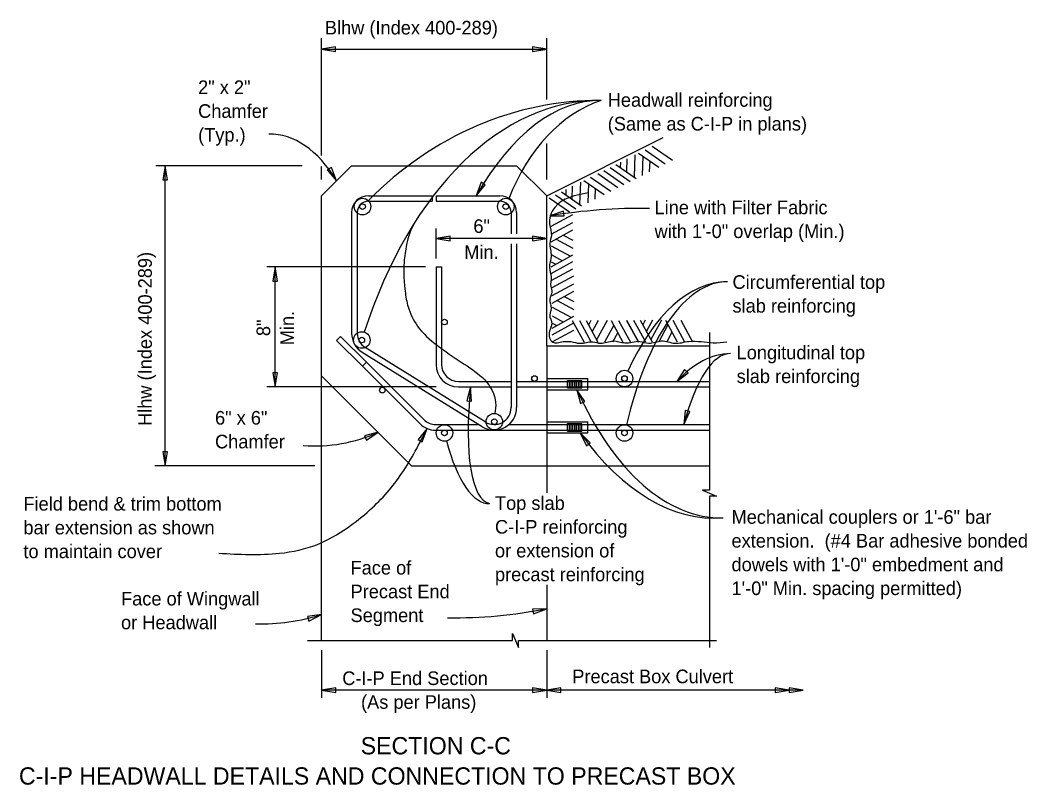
# Model space of a CAD drawing. Extents: x 10575.8 to 10602.6, y 76426.7 to 76442.6.
# Drawn here: x 10576.34 to 10581.93, y 76432.51 to 76436.75 of the extents above; entities that cross this region are included whole.
import ezdxf

# ---------------------------------------------------------------- set-up
doc = ezdxf.new("R2010")
doc.units = 0
for name, color, linetype in [('AdhocPoint_dp', 7, 'Continuous'), ('Miscellaneous', 7, 'Continuous'), ('PlotBorder_dp', 7, 'Continuous'), ('SheetBorder_dp', 7, 'Continuous'), ('TextMisc', 7, 'Continuous')]:
    doc.layers.add(name, color=color, linetype=linetype)

msp = doc.modelspace()

# ---------------------------------------------------------------- linework, layer by layer
at = {"layer": 'AdhocPoint_dp'}
for p, q in [((10578.2711, 76435.7777), (10578.6253, 76435.7777)), ((10578.2711, 76435.7465), (10578.6253, 76435.7465)), ((10578.6253, 76435.7777), (10578.6253, 76435.7465)), ((10578.6461, 76435.7777), (10578.6461, 76435.7465)), ((10578.6461, 76435.7777), (10579.0003, 76435.7777)), ((10578.6461, 76435.7465), (10579.0003, 76435.7465)), ((10578.1774, 76435.684), (10578.1774, 76435.014)), ((10578.2086, 76435.684), (10578.2086, 76435.014)), ((10579.0628, 76435.684), (10579.0628, 76435.5667)), ((10579.094, 76435.684), (10579.094, 76435.5667)), ((10579.0628, 76435.5107), (10579.0628, 76434.6006)), ((10579.094, 76435.5101), (10579.094, 76434.6006)), ((10578.6462, 76435.382), (10578.6462, 76434.8403)), ((10578.6462, 76435.382), (10578.6774, 76435.382)), ((10578.6774, 76435.382), (10578.6774, 76434.8403)), ((10578.094, 76434.9743), (10578.1161, 76434.9963)), ((10578.2381, 76434.8302), (10578.094, 76434.9743)), ((10578.2602, 76434.8523), (10578.1161, 76434.9963)), ((10578.9032, 76434.4944), (10578.2366, 76434.9077)), ((10578.9196, 76434.5209), (10578.253, 76434.9342)), ((10578.2381, 76434.8302), (10578.2602, 76434.8523)), ((10578.5782, 76434.5343), (10578.2602, 76434.8523)), ((10578.5561, 76434.5122), (10578.2381, 76434.8302)), ((10578.7712, 76434.7465), (10579.0628, 76434.7465)), ((10579.094, 76434.7465), (10580.1643, 76434.7465)), ((10578.7712, 76434.7153), (10579.0628, 76434.7153)), ((10579.094, 76434.7153), (10580.1643, 76434.7153)), ((10579.1116, 76434.7153), (10579.2816, 76434.7153)), ((10578.6445, 76434.5068), (10578.8831, 76434.5068)), ((10578.6445, 76434.4756), (10580.1643, 76434.4756)), ((10579.0517, 76434.5068), (10580.1643, 76434.5068))]:
    msp.add_line(p, q, dxfattribs=at)
for centre in [(10578.238, 76435.7172), (10579.0335, 76435.7172), (10578.693, 76435.076), (10578.2341, 76434.9759), (10579.193, 76434.7621), (10579.693, 76434.7621), (10578.3484, 76434.6978), (10578.9699, 76434.5224), (10578.693, 76434.46), (10579.693, 76434.46)]:
    msp.add_circle(centre, 0.0156, dxfattribs=at)
for centre, radius, start, end in [((10578.2711, 76435.684), 0.0937, 90.0004, 179.9995), ((10578.2711, 76435.684), 0.0625, 90, 180), ((10579.0003, 76435.684), 0.0937, 0.0004, 90.0004), ((10579.0003, 76435.684), 0.0625, 0, 90), ((10578.3024, 76435.014), 0.125, 180, 238.196), ((10578.3024, 76435.014), 0.0938, 180, 238.1963), ((10578.7712, 76434.8403), 0.125, 180, 269.9925), ((10578.7712, 76434.8403), 0.0938, 180, 270), ((10578.969, 76434.6006), 0.125, 238.1961, 0), ((10578.969, 76434.6006), 0.0938, 238.1961, 0), ((10578.6445, 76434.6006), 0.125, 225, 269.9925), ((10578.6445, 76434.6006), 0.0938, 225, 270)]:
    msp.add_arc(centre, radius, start, end, dxfattribs=at)
at = {"layer": 'Miscellaneous'}
for p, q in [((10579.2607, 76435.7777), (10579.9073, 76436.101)), ((10579.8073, 76436.0324), (10579.9195, 76435.9546)), ((10579.8469, 76436.0522), (10579.9592, 76435.9744)), ((10579.67, 76435.9637), (10579.669, 76435.9353)), ((10579.7058, 76435.9816), (10579.7033, 76435.9115)), ((10579.7504, 76436.0039), (10579.7457, 76435.882)), ((10579.7702, 76436.0138), (10579.8827, 76435.9361)), ((10579.7951, 76435.9966), (10579.7913, 76435.8905)), ((10579.8329, 76435.9706), (10579.8306, 76435.9101)), ((10579.5775, 76435.9175), (10579.6897, 76435.8396)), ((10579.6125, 76435.935), (10579.7247, 76435.8572)), ((10579.6456, 76435.9515), (10579.7578, 76435.8737)), ((10579.4477, 76435.8524), (10579.443, 76435.7305)), ((10579.4675, 76435.8623), (10579.58, 76435.7846)), ((10579.5046, 76435.8808), (10579.6168, 76435.803)), ((10579.5442, 76435.9006), (10579.6565, 76435.8228)), ((10579.3429, 76435.8), (10579.455, 76435.7221)), ((10579.3673, 76435.8122), (10579.3663, 76435.7837)), ((10579.4031, 76435.8301), (10579.4006, 76435.7599)), ((10579.4924, 76435.8451), (10579.4886, 76435.7389)), ((10579.5301, 76435.819), (10579.5279, 76435.7585)), ((10579.2748, 76435.7659), (10579.387, 76435.6881)), ((10579.3098, 76435.7834), (10579.422, 76435.7056)), ((10579.2863, 76435.608), (10579.4061, 76435.6736)), ((10579.2863, 76435.5637), (10579.4061, 76435.6293)), ((10579.2863, 76435.5222), (10579.4061, 76435.5881)), ((10579.3128, 76435.5368), (10579.4061, 76435.4859)), ((10579.3531, 76435.5589), (10579.4061, 76435.5299)), ((10579.2863, 76435.5001), (10579.3933, 76435.4414)), ((10579.2863, 76435.4502), (10579.348, 76435.4166)), ((10579.2863, 76435.3829), (10579.4061, 76435.4484)), ((10579.2863, 76435.3459), (10579.4061, 76435.4115)), ((10579.2863, 76435.4102), (10579.3114, 76435.3966)), ((10579.2863, 76435.3068), (10579.4061, 76435.3723)), ((10579.2917, 76435.2674), (10579.4115, 76435.333)), ((10579.2917, 76435.2231), (10579.4115, 76435.2886)), ((10579.2917, 76435.1816), (10579.4115, 76435.2475)), ((10579.3182, 76435.1962), (10579.4115, 76435.1453)), ((10579.3584, 76435.2183), (10579.4115, 76435.1892)), ((10579.2917, 76435.1594), (10579.3986, 76435.1007)), ((10579.2917, 76435.1096), (10579.3533, 76435.076)), ((10579.2917, 76435.0422), (10579.4115, 76435.1078)), ((10579.2917, 76435.0053), (10579.4115, 76435.0708)), ((10579.2917, 76435.0696), (10579.3167, 76435.0559)), ((10579.4031, 76435.0844), (10579.4686, 76434.9646)), ((10579.4423, 76435.0844), (10579.5078, 76434.9646)), ((10579.4793, 76435.0844), (10579.5448, 76434.9646)), ((10579.5066, 76435.0844), (10579.4929, 76435.0593)), ((10579.5466, 76435.0844), (10579.513, 76435.0227)), ((10579.5964, 76435.0844), (10579.5377, 76434.9774)), ((10579.6186, 76435.0844), (10579.6845, 76434.9646)), ((10579.6601, 76435.0844), (10579.7256, 76434.9646)), ((10579.7044, 76435.0864), (10579.77, 76434.9666)), ((10579.7044, 76435.0844), (10579.77, 76434.9646)), ((10579.7436, 76435.0864), (10579.8092, 76434.9666)), ((10579.7806, 76435.0864), (10579.8461, 76434.9666)), ((10579.8079, 76435.0864), (10579.7943, 76435.0613)), ((10579.8479, 76435.0864), (10579.8143, 76435.0247)), ((10579.8977, 76435.0864), (10579.8391, 76434.9794)), ((10579.9199, 76435.0864), (10579.9858, 76434.9666)), ((10579.9614, 76435.0864), (10580.027, 76434.9666)), ((10580.0057, 76435.0864), (10580.0713, 76434.9666)), ((10579.2917, 76434.9661), (10579.4115, 76435.0316)), ((10579.6332, 76435.0579), (10579.5823, 76434.9646)), ((10579.6553, 76435.0176), (10579.6262, 76434.9646)), ((10579.9345, 76435.0599), (10579.8836, 76434.9666)), ((10579.9566, 76435.0197), (10579.9275, 76434.9666)), ((10579.2607, 76434.7619), (10579.4895, 76434.7619)), ((10579.3767, 76434.7517), (10579.4167, 76434.7517)), ((10579.3767, 76434.71), (10579.3767, 76434.7517)), ((10579.3867, 76434.71), (10579.3867, 76434.7517)), ((10579.3967, 76434.71), (10579.3967, 76434.7517)), ((10579.4067, 76434.71), (10579.4067, 76434.7517)), ((10579.4167, 76434.7517), (10579.4567, 76434.7517)), ((10579.4167, 76434.71), (10579.4167, 76434.7517)), ((10579.4267, 76434.71), (10579.4267, 76434.7517)), ((10579.4367, 76434.71), (10579.4367, 76434.7517)), ((10579.4467, 76434.71), (10579.4467, 76434.7517)), ((10579.4567, 76434.71), (10579.4567, 76434.7517)), ((10579.2607, 76434.6998), (10579.4895, 76434.6998)), ((10579.3767, 76434.71), (10579.4167, 76434.71)), ((10579.4167, 76434.71), (10579.4567, 76434.71)), ((10579.2607, 76434.5222), (10579.4895, 76434.5222)), ((10579.3767, 76434.512), (10579.4567, 76434.512)), ((10579.3767, 76434.4703), (10579.3767, 76434.512)), ((10579.3867, 76434.4703), (10579.3867, 76434.512)), ((10579.3967, 76434.4703), (10579.3967, 76434.512)), ((10579.4067, 76434.4703), (10579.4067, 76434.512)), ((10579.4167, 76434.4703), (10579.4167, 76434.512)), ((10579.4267, 76434.4703), (10579.4267, 76434.512)), ((10579.4367, 76434.4703), (10579.4367, 76434.512)), ((10579.4467, 76434.4703), (10579.4467, 76434.512)), ((10579.4567, 76434.4703), (10579.4567, 76434.512)), ((10579.2607, 76434.4601), (10579.4895, 76434.4601)), ((10579.3767, 76434.4703), (10579.4567, 76434.4703))]:
    msp.add_line(p, q, dxfattribs=at)
for points in [[(10579.4895, 76434.6998), (10579.4895, 76434.7619)], [(10579.4895, 76434.4601), (10579.4895, 76434.5222)]]:
    msp.add_lwpolyline(points, dxfattribs=at)
msp.add_spline([(10579.4935, 76435.794), (10579.3054, 76435.7126), (10579.2768, 76435.6173), (10579.287, 76435.5575), (10579.2781, 76435.5143), (10579.2858, 76435.443), (10579.2756, 76435.3794), (10579.2858, 76435.326), (10579.2832, 76435.2738), (10579.2896, 76435.242), (10579.2781, 76435.2026), (10579.2858, 76435.153), (10579.2781, 76435.1033), (10579.2883, 76435.0792), (10579.2768, 76435.0257), (10579.2953, 76434.9636), (10579.3189, 76434.9614), (10579.3532, 76434.9672), (10579.3952, 76434.9672), (10579.4448, 76434.9583), (10579.5173, 76434.9659), (10579.5593, 76434.9583), (10579.6305, 76434.971), (10579.6941, 76434.9596), (10579.7781, 76434.9685), (10579.8277, 76434.9583), (10579.899, 76434.971), (10579.9715, 76434.9583), (10580.0504, 76434.9685), (10580.186, 76434.9609), (10580.2607, 76434.9652)], degree=3, dxfattribs=at)
at = {"layer": 'PlotBorder_dp'}
for p, q in [((10578.1774, 76435.9444), (10578.0107, 76435.7777)), ((10578.1774, 76435.9444), (10579.094, 76435.9444)), ((10579.2607, 76435.7777), (10579.094, 76435.9444)), ((10578.0107, 76434.7777), (10578.0107, 76435.7777)), ((10579.2607, 76434.9444), (10579.2607, 76435.7777)), ((10579.2607, 76434.9444), (10580.1643, 76434.9444)), ((10579.2607, 76434.9444), (10579.2607, 76434.1278)), ((10578.0107, 76433.3069), (10578.0107, 76434.7777)), ((10578.5107, 76434.2777), (10578.0107, 76434.7777)), ((10578.5107, 76434.2777), (10580.1643, 76434.2777)), ((10579.2607, 76433.6169), (10579.2607, 76433.3069))]:
    msp.add_line(p, q, dxfattribs=at)
at = {"layer": 'TextMisc'}
for p, q in [((10578.0107, 76436.0018), (10578.0107, 76436.6519)), ((10579.2607, 76436.3125), (10579.2607, 76436.6519)), ((10578.0107, 76436.5914), (10579.2607, 76436.5914)), ((10579.2607, 76435.867), (10579.2607, 76436.0669)), ((10577.9023, 76435.9444), (10577.0896, 76435.9444)), ((10577.1421, 76434.2777), (10577.1421, 76435.9444)), ((10578.0107, 76435.867), (10578.0107, 76435.9393)), ((10578.6462, 76435.4296), (10578.6462, 76435.5953)), ((10579.2607, 76435.5404), (10578.6462, 76435.5404)), ((10578.5883, 76435.382), (10577.707, 76435.382)), ((10577.7534, 76434.7153), (10577.7534, 76435.382)), ((10578.6473, 76434.7153), (10577.707, 76434.7153)), ((10577.9732, 76434.2777), (10577.085, 76434.2777)), ((10578.0108, 76433.2537), (10578.0108, 76432.9879)), ((10579.2607, 76433.2537), (10579.2607, 76432.9879)), ((10579.2607, 76433.0317), (10578.0108, 76433.0317)), ((10580.6851, 76433.0317), (10579.2607, 76433.0317))]:
    msp.add_line(p, q, dxfattribs=at)
for points in [[(10578.0107, 76436.5914), (10578.0888, 76436.5781), (10578.0888, 76436.6046)], [(10579.2607, 76436.5914), (10579.1826, 76436.6046), (10579.1826, 76436.5781)], [(10577.1421, 76435.9444), (10577.1289, 76435.8663), (10577.1554, 76435.8663)], [(10578.0941, 76435.861), (10578.0648, 76435.9346), (10578.0422, 76435.9208)], [(10578.8685, 76435.7777), (10578.919, 76435.8388), (10578.896, 76435.852)], [(10579.2782, 76435.6661), (10579.3574, 76435.6654), (10579.3533, 76435.6915)], [(10578.6462, 76435.5404), (10578.7243, 76435.5272), (10578.7243, 76435.5537)], [(10579.2607, 76435.5404), (10579.1827, 76435.5537), (10579.1827, 76435.5272)], [(10577.7534, 76435.382), (10577.7402, 76435.3039), (10577.7666, 76435.3039)], [(10577.7534, 76434.7153), (10577.7666, 76434.7934), (10577.7402, 76434.7934)], [(10579.983, 76434.7465), (10580.0458, 76434.7947), (10580.0264, 76434.8127)], [(10578.8378, 76434.7153), (10578.8172, 76434.6388), (10578.8436, 76434.6363)], [(10579.4285, 76434.6998), (10579.4487, 76434.6233), (10579.4728, 76434.6342)], [(10580.0218, 76434.5068), (10580.0554, 76434.5785), (10580.0299, 76434.5856)], [(10578.3249, 76434.4635), (10578.2483, 76434.4435), (10578.2592, 76434.4193)], [(10578.5967, 76434.4851), (10578.5469, 76434.4235), (10578.5699, 76434.4105)], [(10579.4458, 76434.4602), (10579.4811, 76434.3892), (10579.5025, 76434.4048)], [(10577.1421, 76434.2777), (10577.1554, 76434.3558), (10577.1289, 76434.3558)], [(10578.0107, 76433.4516), (10577.9323, 76433.4407), (10577.9403, 76433.4154)], [(10579.2607, 76433.4838), (10579.1816, 76433.4816), (10579.1867, 76433.4556)], [(10578.0108, 76433.0317), (10578.0889, 76433.0185), (10578.0889, 76433.045)], [(10579.2607, 76433.0317), (10579.1826, 76433.045), (10579.1826, 76433.0185)], [(10579.2607, 76433.0317), (10579.3388, 76433.0185), (10579.3388, 76433.045)], [(10580.607, 76433.0317), (10580.5289, 76433.0449), (10580.5289, 76433.0185)], [(10580.6851, 76433.0317), (10580.607, 76433.0449), (10580.607, 76433.0185)]]:
    msp.add_lwpolyline(points, close=True, dxfattribs=at)
for points in [[(10580.1643, 76435.0183), (10580.1643, 76434.1425), (10580.1256, 76434.1425), (10580.1643, 76434.1256), (10580.2031, 76434.1088), (10580.1643, 76434.1088), (10580.1643, 76433.2682)], [(10577.9329, 76433.3069), (10579.0707, 76433.3069), (10579.0707, 76433.3457), (10579.0875, 76433.3069), (10579.1044, 76433.2682), (10579.1044, 76433.3069), (10580.2031, 76433.3069)]]:
    msp.add_lwpolyline(points, dxfattribs=at)
for centre in [(10578.238, 76435.7172), (10579.0335, 76435.7172), (10578.2341, 76434.9759), (10579.693, 76434.7621), (10578.9699, 76434.5224), (10578.693, 76434.46), (10579.693, 76434.46)]:
    msp.add_circle(centre, 0.0459, dxfattribs=at)
for centre, radius, start, end in [((10579.7979, 76432.4047), 3.3027, 89.3971, 99.0535), ((10577.974, 76435.2424), 0.8544, 265.6433, 294.2521), ((10577.6726, 76434.5198), 1.1204, 268.5413, 287.5651), ((10578.7448, 76436.0849), 2.6517, 269.2568, 281.2187)]:
    msp.add_arc(centre, radius, start, end, dxfattribs=at)
for centre, major_axis, ratio, start_param, end_param in [((10579.5386, 76433.9453), (-0.0243, -2.3612), 0.617071, 3.141593, 4.246347), ((10579.5456, 76434.0646), (-0.0172, -2.2419), 0.865159, 3.141593, 3.868244), ((10579.5374, 76433.8778), (-0.0255, -2.4287), 0.452522, 3.141593, 3.818879), ((10580.2263, 76434.3769), (0.6635, -1.9296), 0.580134, 3.141593, 3.735964), ((10577.738, 76435.1727), (0.0202, -0.9471), 0.562458, 2.372304, 3.141593), ((10580.2816, 76433.6398), (0.0171, -1.6604), 0.402699, 3.141593, 4.160334), ((10580.2816, 76433.6398), (0.0171, -1.6604), 0.473544, 3.141593, 3.930463), ((10580.315, 76433.1838), (0.0343, -1.7172), 0.430483, 3.141593, 3.560489), ((10580.315, 76433.1838), (0.0343, -1.7172), 0.245056, 3.141593, 3.827956), ((10579.2419, 76435.2906), (0.2985, 1.223), 0.238216, 2.117736, 3.141593), ((10580.2012, 76436.0287), (-0.0394, 2.0403), 0.511198, 2.270212, 3.141593), ((10580.0516, 76436.2296), (-0.1891, 2.2412), 0.515902, 2.436127, 3.141593), ((10578.9146, 76434.8786), (-0.0288, 0.811), 0.337532, 2.166568, 3.141593)]:
    msp.add_ellipse(centre, major_axis=major_axis, ratio=ratio, start_param=start_param, end_param=end_param, dxfattribs=at)
for points in [[(10578.5286, 76435.6305), (10578.5003, 76435.5699), (10578.4828, 76435.5058), (10578.4688, 76435.409), (10578.4758, 76435.2369), (10578.4948, 76435.149), (10578.5534, 76435.0404), (10578.6706, 76434.9334), (10578.8033, 76434.8422), (10578.9164, 76434.7543), (10578.9774, 76434.6285), (10578.9731, 76434.5682)], [(10577.4399, 76433.7918), (10577.7774, 76433.7918), (10577.9871, 76433.8408), (10578.154, 76433.9337), (10578.2793, 76434.0323), (10578.4572, 76434.2369), (10578.5967, 76434.4851)]]:
    msp.add_spline(points, degree=3, dxfattribs=at)

# ---------------------------------------------------------------- texts
at = {"layer": 'SheetBorder_dp'}
for s, height, p in [('Blhw (Index 400-289)', 0.0756, (10578.029, 76436.6732)), ('2" x 2" ', 0.0756, (10577.3249, 76436.3421)), ('Headwall reinforcing', 0.0756, (10579.5998, 76436.2716)), ('Chamfer', 0.0756, (10577.3249, 76436.2101)), ('(Same as C-I-P in plans)', 0.0756, (10579.5998, 76436.1396)), ('(Typ.)', 0.0756, (10577.3249, 76436.0781)), ('Line with Filter Fabric', 0.0756, (10579.8598, 76435.6746)), ('6"', 0.0756, (10578.8535, 76435.571)), ('with 1\'-0" overlap (Min.)', 0.0756, (10579.8598, 76435.5426)), ('Min.', 0.0756, (10578.8028, 76435.427)), ('Circumferential top', 0.0756, (10580.2926, 76435.2603)), ('slab reinforcing', 0.0756, (10580.2926, 76435.1283)), ('Longitudinal top', 0.0756, (10580.3156, 76434.869)), ('slab reinforcing', 0.0756, (10580.3156, 76434.737)), ('6" x 6"', 0.0756, (10577.4188, 76434.5064)), ('Chamfer', 0.0756, (10577.4188, 76434.3744)), ('Field bend & trim bottom', 0.0756, (10576.3547, 76434.0287)), ('Top slab', 0.0756, (10578.9735, 76434.0327)), ('Mechanical couplers or 1\'-6" bar', 0.0756, (10580.2873, 76433.9556)), ('bar extension as shown', 0.0756, (10576.3547, 76433.8967)), ('C-I-P reinforcing', 0.0756, (10578.9735, 76433.9007)), ('extension.  (#4 Bar adhesive bonded', 0.0756, (10580.2873, 76433.8236)), ('to maintain cover', 0.0756, (10576.3547, 76433.7647)), ('or extension of', 0.0756, (10578.9735, 76433.7687)), ('Face of', 0.0756, (10578.1715, 76433.6737)), ('dowels with 1\'-0" embedment and', 0.0756, (10580.2873, 76433.6916)), ('precast reinforcing', 0.0756, (10578.9735, 76433.6367)), ('Precast End', 0.0756, (10578.1715, 76433.5417)), ('1\'-0" Min. spacing permitted)', 0.0756, (10580.2873, 76433.5596)), ('Face of Wingwall', 0.0756, (10576.8968, 76433.5018)), ('or Headwall', 0.0756, (10576.8968, 76433.3698)), ('Segment', 0.0756, (10578.1715, 76433.4097)), ('C-I-P End Section', 0.0756, (10578.1253, 76433.0599)), ('Precast Box Culvert', 0.0756, (10579.403, 76433.0699)), ('(As per Plans)', 0.0756, (10578.2297, 76432.9279)), ('SECTION C-C', 0.096, (10578.2278, 76432.6748)), ('C-I-P HEADWALL DETAILS AND CONNECTION TO PRECAST BOX', 0.096, (10576.3299, 76432.5068))]:
    msp.add_text(s, height=height, dxfattribs=at).set_placement(p)
for s, p in [('Hlhw (Index 400-289)', (10577.0677, 76434.499)), ('Min.', (10577.8572, 76434.947)), ('8"', (10577.7252, 76434.9978))]:
    msp.add_text(s, height=0.0756, rotation=90, dxfattribs=at).set_placement(p)

doc.saveas('drawing.dxf')
